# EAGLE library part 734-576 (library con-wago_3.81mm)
Serie 734, Federleiste mit abgewinkelten Einlötstiften / Series 734, Female connector with angled solder pins Polzahl / Pole No.: 16 Bemessungsspannung / Rated Voltage: 160 V Nennstrom / Nominal Current: 10 A Lötstiftlänge: / Solder Pin Length: 3.8 mm Farbe / Color: orange / orange Stand: 01.01.2012. Die jeweils aktuellen Daten zu diesem Artikel finden Sie in unserem Produktkatalog, den Sie unter www.wago.com einsehen können. As of: 01/01/2012. Please find the newest data for this article in our product catalogue, which can be viewed under www.wago.com.
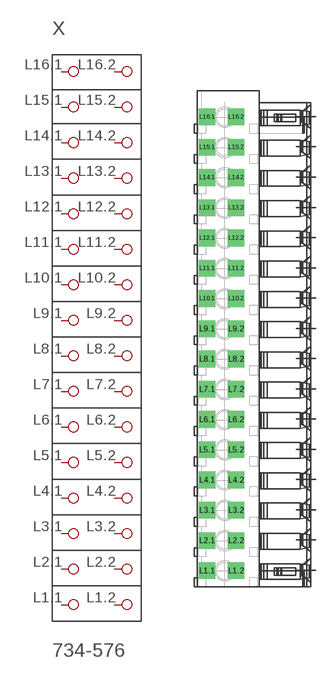
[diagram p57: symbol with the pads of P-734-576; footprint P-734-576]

Designator prefix X

## 734-576  [P-734-576]
L1.1  P1.1
L1.2  P1.2
L2.1  P2.1
L2.2  P2.2
L3.1  P3.1
L3.2  P3.2
L4.1  P4.1
L4.2  P4.2
L5.1  P5.1
L5.2  P5.2
L6.1  P6.1
L6.2  P6.2
L7.1  P7.1
L7.2  P7.2
L8.1  P8.1
L8.2  P8.2
L9.1  P9.1
L9.2  P9.2
L10.1  P10.1
L10.2  P10.2
L11.1  P11.1
L11.2  P11.2
L12.1  P12.1
L12.2  P12.2
L13.1  P13.1
L13.2  P13.2
L14.1  P14.1
L14.2  P14.2
L15.1  P15.1
L15.2  P15.2
L16.1  P16.1
L16.2  P16.2

## Footprint P-734-576 (pad centres in mm)
drill 1.4 square: L1.1 -6.052,-29.22; L1.2 -2.402,-29.22; L2.1 -6.052,-25.41; L2.2 -2.402,-25.41; L3.1 -6.052,-21.6; L3.2 -2.402,-21.6; L4.1 -6.052,-17.79; L4.2 -2.402,-17.79; L5.1 -6.052,-13.98; L5.2 -2.402,-13.98; L6.1 -6.052,-10.17; L6.2 -2.402,-10.17; L7.1 -6.052,-6.36; L7.2 -2.402,-6.36; L8.1 -6.052,-2.55; L8.2 -2.402,-2.55; L9.1 -6.052,1.26; L9.2 -2.402,1.26; L10.1 -6.052,5.07; L10.2 -2.402,5.07; L11.1 -6.052,8.88; L11.2 -2.402,8.88; L12.1 -6.052,12.69; L12.2 -2.402,12.69; L13.1 -6.052,16.5; L13.2 -2.402,16.5; L14.1 -6.052,20.31; L14.2 -2.402,20.31; L15.1 -6.052,24.12; L15.2 -2.402,24.12; L16.1 -6.052,27.93; L16.2 -2.402,27.93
